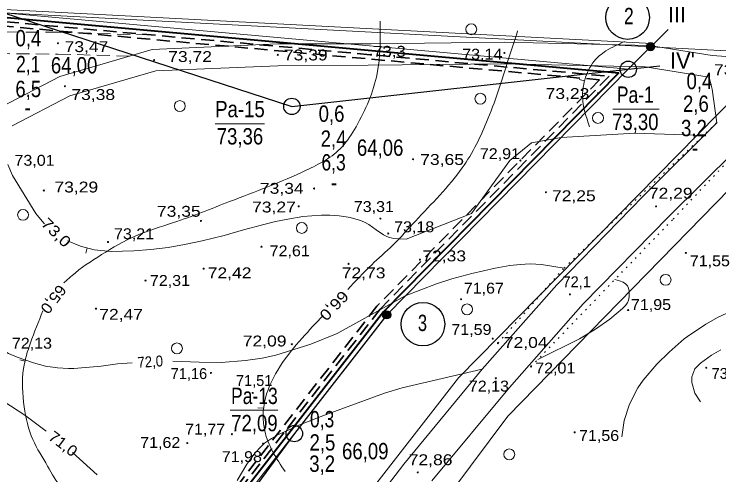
# Model space of a CAD drawing. Extents: x 628176 to 629009, y 6439913 to 6440496.
# Drawn here: x 628597 to 628726.4, y 6440342 to 6440426.6 of the extents above; entities that cross this region are included whole.
import ezdxf
from ezdxf.enums import TextEntityAlignment as Align

# ---------------------------------------------------------------- set-up
doc = ezdxf.new("R2010")
doc.units = 0
doc.header["$LTSCALE"] = 0.8
doc.linetypes.add('DOTTED', pattern=[1.5, 0.3, -1.2])
doc.linetypes.add('MEDIUM_DASHED', pattern=[4.5, 3, -1.5])
for name, color, linetype, lineweight in [('1', 7, 'Continuous', 13), ('10', 7, 'Continuous', 25), ('11', 7, 'Continuous', 13), ('12', 7, 'Continuous', 13), ('14', 7, 'Continuous', 25), ('16', 7, 'Continuous', 13), ('21', 7, 'MEDIUM_DASHED', 35), ('3', 7, 'Continuous', 13), ('6', 7, 'Continuous', 13)]:
    doc.layers.add(name, color=color, linetype=linetype, lineweight=lineweight)

msp = doc.modelspace()

# ---------------------------------------------------------------- hatches: boundary and pattern name
at = {"layer": '1'}
for points in [[(628605.1533, 6440421.2963, 1), (628604.9533, 6440421.2963, 1)], [(628687.1286, 6440419.5224, 1), (628686.9286, 6440419.5224, 1)], [(628622.7972, 6440418.1965, 1), (628622.5972, 6440418.1965, 1)], [(628645.5127, 6440419.1617, 1), (628645.3127, 6440419.1617, 1)], [(628662.6431, 6440419.1946, 1), (628662.4431, 6440419.1946, 1)], [(628606.4316, 6440413.4012, 1), (628606.2316, 6440413.4012, 1)], [(628704.3235, 6440412.1118, 1), (628704.1235, 6440412.1118, 1)], [(628670.3441, 6440399.9828, 1), (628670.1441, 6440399.9828, 1)], [(628690.0527, 6440399.7621, 1), (628689.8527, 6440399.7621, 1)], [(628602.5603, 6440394.2498, 1), (628602.3603, 6440394.2498, 1)], [(628652.1703, 6440394.6068, 1), (628651.9703, 6440394.6068, 1)], [(628694.7513, 6440393.9231, 1), (628694.5513, 6440393.9231, 1)], [(628649.3441, 6440391.3336, 1), (628649.1441, 6440391.3336, 1)], [(628714.9724, 6440391.3156, 1), (628714.7724, 6440391.3156, 1)], [(628631.4097, 6440388.6483, 1), (628631.2097, 6440388.6483, 1)], [(628664.365, 6440389.093, 1), (628664.165, 6440389.093, 1)], [(628665.8023, 6440386.3436, 1), (628665.6023, 6440386.3436, 1)], [(628614.341, 6440384.7869, 1), (628614.141, 6440384.7869, 1)], [(628642.5216, 6440383.9258, 1), (628642.3216, 6440383.9258, 1)], [(628720.4395, 6440382.7761, 1), (628720.2395, 6440382.7761, 1)], [(628658.5177, 6440380.7809, 1), (628658.3177, 6440380.7809, 1)], [(628671.6151, 6440381.5439, 1), (628671.4151, 6440381.5439, 1)], [(628631.9196, 6440379.8836, 1), (628631.7196, 6440379.8836, 1)], [(628621.2287, 6440377.6988, 1), (628621.0287, 6440377.6988, 1)], [(628679.1774, 6440374.2655, 1), (628678.9774, 6440374.2655, 1)], [(628699.1563, 6440375.1665, 1), (628698.9563, 6440375.1665, 1)], [(628612.1476, 6440372.5403, 1), (628611.9476, 6440372.5403, 1)], [(628709.8488, 6440372.2932, 1), (628709.6488, 6440372.2932, 1)], [(628684.9805, 6440367.0306, 1), (628684.7805, 6440367.0306, 1)], [(628685.9305, 6440366.2029, 1), (628685.7305, 6440366.2029, 1)], [(628648.0999, 6440365.9999, 1), (628647.8999, 6440365.9999, 1)], [(628692.0232, 6440361.8986, 1), (628691.8232, 6440361.8986, 1)], [(628724.1856, 6440361.6868, 1), (628723.9856, 6440361.6868, 1)], [(628633.2561, 6440360.7317, 1), (628633.0561, 6440360.7317, 1)], [(628685.5521, 6440359.7429, 1), (628685.3521, 6440359.7429, 1)], [(628640.9094, 6440357.0609, 1), (628640.7094, 6440357.0609, 1)], [(628637.0978, 6440349.4856, 1), (628636.8978, 6440349.4856, 1)], [(628700.0247, 6440349.8142, 1), (628699.8247, 6440349.8142, 1)], [(628628.9037, 6440347.8529, 1), (628628.7037, 6440347.8529, 1)], [(628642.8255, 6440347.757, 1), (628642.6255, 6440347.757, 1)], [(628671.218, 6440342.4629, 1), (628671.018, 6440342.4629, 1)]]:
    msp.add_hatch(color=256, dxfattribs=at).paths.add_polyline_path(points)
at = {"layer": '10'}
for points in [[(628714.5881, 6440420.6605, 1), (628713.0881, 6440420.6605, 1)], [(628666.1574, 6440371.4031, 1), (628664.6574, 6440371.4031, 1)]]:
    msp.add_hatch(color=256, dxfattribs=at).paths.add_polyline_path(points)

# ---------------------------------------------------------------- linework, layer by layer
at = {"layer": '1', "linetype": 'MEDIUM_DASHED'}
for p, q in [((628577.55, 6440423.51), (628605.07, 6440423.3)), ((628605.11, 6440423.3), (628621.66, 6440422.82)), ((628579.42, 6440419.49), (628605.04, 6440419.3)), ((628605, 6440419.3), (628618.11, 6440418.92))]:
    msp.add_line(p, q, dxfattribs=at)
at = {"layer": '1'}
for p, q in [((628645.41, 6440421.16), (628622.34, 6440420.16)), ((628662.54, 6440421.19), (628645.41, 6440421.16)), ((628687.03, 6440421.52), (628662.54, 6440421.19)), ((628713.68, 6440420.86), (628687.03, 6440421.52)), ((628725.2, 6440419.05), (628713.68, 6440420.86)), ((628622.34, 6440420.16), (628605.41, 6440415.18)), ((628737.64, 6440418.15), (628725.2, 6440419.05)), ((628645.41, 6440417.16), (628623.05, 6440416.23)), ((628662, 6440417.27), (628645.41, 6440417.16)), ((628687.03, 6440417.52), (628662, 6440417.27)), ((628712.88, 6440416.94), (628687.03, 6440417.52)), ((628724.62, 6440415.09), (628712.88, 6440416.94)), ((628623.05, 6440416.23), (628607.25, 6440411.62)), ((628605.41, 6440415.18), (628594.58, 6440409.55)), ((628725.14, 6440412.88), (628724.62, 6440415.09)), ((628726.04, 6440406.7), (628725.14, 6440412.88)), ((628607.25, 6440411.62), (628596.67, 6440406.14)), ((628712.53, 6440393.19), (628726.08, 6440406.74)), ((628717.21, 6440389.44), (628730.57, 6440402.75)), ((628696.63, 6440376.93), (628712.53, 6440393.19)), ((628701.48, 6440373.4), (628717.21, 6440389.44)), ((628682.96, 6440361.42), (628696.63, 6440376.93)), ((628687.94, 6440358.07), (628701.48, 6440373.4)), ((628668.54, 6440344), (628682.96, 6440361.42)), ((628673.69, 6440340.93), (628687.94, 6440358.07)), ((628658.58, 6440330.86), (628668.54, 6440344))]:
    msp.add_line(p, q, dxfattribs=at)
at = {"layer": '1', "linetype": 'DOTTED', "lineweight": 25}
for points in [[(628691.92, 6440361.9), (628718, 6440389), (628737.89, 6440410)], [(628685.83, 6440366.2), (628698, 6440380), (628726.08, 6440406.74)]]:
    msp.add_lwpolyline(points, dxfattribs=at)
at = {"layer": '1'}
for centre, radius in [((628680.9407, 6440423.8523), 1), ((628605.0533, 6440421.2963), 0.1), ((628687.0286, 6440419.5224), 0.1), ((628622.6972, 6440418.1965), 0.1), ((628645.4127, 6440419.1617), 0.1), ((628662.5431, 6440419.1946), 0.1), ((628606.3316, 6440413.4012), 0.1), ((628682.6148, 6440411.0956), 1), ((628704.2235, 6440412.1118), 0.1), ((628627.4365, 6440409.7628), 1), ((628704.208, 6440407.5652), 1), ((628670.2441, 6440399.9828), 0.1), ((628689.9527, 6440399.7621), 0.1), ((628602.4603, 6440394.2498), 0.1), ((628652.0703, 6440394.6068), 0.1), ((628694.6513, 6440393.9231), 0.1), ((628649.2441, 6440391.3336), 0.1), ((628714.8724, 6440391.3156), 0.1), ((628598.6478, 6440389.7706), 1), ((628631.3097, 6440388.6483), 0.1), ((628649.8277, 6440387.3716), 1), ((628664.265, 6440389.093), 0.1), ((628665.7023, 6440386.3436), 0.1), ((628614.241, 6440384.7869), 0.1), ((628642.4216, 6440383.9258), 0.1), ((628720.3395, 6440382.7761), 0.1), ((628658.4177, 6440380.7809), 0.1), ((628671.5151, 6440381.5439), 0.1), ((628631.8196, 6440379.8836), 0.1), ((628716.6172, 6440377.8348), 1), ((628621.1287, 6440377.6988), 0.1), ((628679.0774, 6440374.2655), 0.1), ((628699.0563, 6440375.1665), 0.1), ((628680.1651, 6440372.4058), 1), ((628612.0476, 6440372.5403), 0.1), ((628709.7488, 6440372.2932), 0.1), ((628626.9034, 6440365.2469), 1), ((628684.8805, 6440367.0306), 0.1), ((628685.8305, 6440366.2029), 0.1), ((628647.9999, 6440365.9999), 0.1), ((628691.9232, 6440361.8986), 0.1), ((628724.0856, 6440361.6868), 0.1), ((628633.1561, 6440360.7317), 0.1), ((628685.4521, 6440359.7429), 0.1), ((628640.8094, 6440357.0609), 0.1), ((628636.9978, 6440349.4856), 0.1), ((628699.9247, 6440349.8142), 0.1), ((628628.8037, 6440347.8529), 0.1), ((628642.7255, 6440347.757), 0.1), ((628687.9209, 6440345.7776), 1), ((628671.118, 6440342.4629), 0.1)]:
    msp.add_circle(centre, radius, dxfattribs=at)
at = {"layer": '10'}
for centre, radius in [((628709.6526, 6440426.0059), 4), ((628713.8381, 6440420.6605), 0.75), ((628672.0763, 6440369.6895), 4), ((628665.4074, 6440371.4031), 0.75)]:
    msp.add_circle(centre, radius, dxfattribs=at)
at = {"layer": '11'}
msp.add_line((628595.11, 6440426.87), (628709.76, 6440416.52), dxfattribs=at)
for points in [[(628595.11, 6440426.87), (628713.84, 6440420.66), (628709.76, 6440416.52)], [(628709.76, 6440416.52), (628665.41, 6440371.4), (628640.59, 6440339.47), (628612.95, 6440301.12), (628547.63, 6440210.77)]]:
    msp.add_lwpolyline(points, dxfattribs=at)
at = {"layer": '12'}
for p, q in [((628706.94, 6440409.2), (628715.43, 6440409.2)), ((628633.92, 6440406.47), (628643, 6440406.47)), ((628636.7, 6440353.92), (628645.42, 6440353.92))]:
    msp.add_line(p, q, dxfattribs=at)
at = {"layer": '12', "lineweight": 25}
for centre in [(628709.7629, 6440416.5158), (628647.9999, 6440409.6877), (628648.457, 6440349.5935)]:
    msp.add_circle(centre, 1.5, dxfattribs=at)
at = {"layer": '14'}
for q in [(628717.1, 6440423.79), (628715.56, 6440417.12)]:
    msp.add_line((628709.76, 6440416.52), q, dxfattribs=at)
for points in [[(628544.36, 6440425.1), (628595.11, 6440426.87), (628648, 6440409.69), (628709.76, 6440416.52)], [(628709.76, 6440416.52), (628665.41, 6440371.4), (628648.46, 6440349.59)], [(628648.46, 6440349.59), (628617.39, 6440307.28), (628547.63, 6440210.77), (628497.5, 6440118.54), (628474.19, 6440080.39)]]:
    msp.add_lwpolyline(points, dxfattribs=at)
at = {"layer": '16'}
for p, q in [((628700.77, 6440414.65), (628701.72, 6440414.36)), ((628598.03, 6440363.13), (628599.01, 6440362.9)), ((628641.78, 6440354.35), (628642.78, 6440354.27))]:
    msp.add_line(p, q, dxfattribs=at)
for points in [[(628664.23, 6440425.32), (628663.66, 6440415.72), (628659.79, 6440405.97), (628657.21, 6440402.25), (628650.62, 6440397.95), (628636.57, 6440392.21), (628626.25, 6440388.34), (628619.37, 6440385.91), (628613.06, 6440382.47), (628607.61, 6440378.6), (628606.11, 6440377.27)], [(628689.46, 6440423.6), (628688.03, 6440419.16), (628684.01, 6440407.41), (628679.28, 6440398.38), (628670.68, 6440388.63), (628666.53, 6440384.19), (628662.66, 6440380.6), (628658.25, 6440376.03)], [(628709.1, 6440421.6), (628705.66, 6440419.88), (628703.51, 6440418.01), (628701.79, 6440414.57), (628701.36, 6440411.42), (628702.65, 6440405.97)], [(628602.3, 6440372.11), (628600.02, 6440366.27), (628598.73, 6440361.54), (628598.87, 6440354.51), (628600.45, 6440348.49), (628603.17, 6440343.62), (628605.75, 6440339.61), (628610.62, 6440336.31), (628614.49, 6440334.3), (628621.23, 6440330.15), (628624.24, 6440328.14), (628629.83, 6440322.98)], [(628653.74, 6440371.29), (628649.9, 6440367.13), (628643.16, 6440356.09), (628642.73, 6440352.79), (628643.02, 6440350.07), (628646.75, 6440342.62)]]:
    msp.add_spline(points, degree=3, dxfattribs=at)
at = {"layer": '21'}
for p, q in [((628594.53, 6440424.51), (628704.5, 6440414.58)), ((628595.48, 6440425.23), (628706.25, 6440415.23))]:
    msp.add_line(p, q, dxfattribs=at)
at = {"layer": '21', "linetype": 'Continuous', "lineweight": 40}
for points in [[(628544.47, 6440424.31), (628575.21, 6440427.11), (628595.05, 6440426.07), (628708.01, 6440415.87)], [(628708.01, 6440415.87), (628664.8, 6440371.93), (628639.95, 6440339.95), (628612.3, 6440301.59), (628546.94, 6440211.19)]]:
    msp.add_lwpolyline(points, dxfattribs=at)
at = {"layer": '21'}
for points in [[(628704.5, 6440414.58), (628663.6, 6440372.99), (628638.67, 6440340.91), (628611, 6440302.53), (628546.02, 6440212.64)], [(628706.25, 6440415.23), (628664.2, 6440372.46), (628639.31, 6440340.43), (628611.65, 6440302.06), (628547.03, 6440212.69)]]:
    msp.add_lwpolyline(points, dxfattribs=at)
at = {"layer": '3'}
for p, q in [((628711, 6440404.75), (628723.71, 6440404.37)), ((628681, 6440390), (628688, 6440399.78)), ((628656.66, 6440389.59), (628654.97, 6440389.71)), ((628669, 6440385.32), (628681, 6440390)), ((628602.46, 6440388.25), (628602.6, 6440388.12)), ((628642.87, 6440388), (628645, 6440388.52)), ((628647.29, 6440389), (628645, 6440388.52)), ((628635.58, 6440386), (628639.14, 6440387)), ((628639.14, 6440387), (628642.87, 6440388)), ((628631.56, 6440385), (628635.58, 6440386)), ((628610.16, 6440382.72), (628610.41, 6440383.69)), ((628622.1, 6440383.39), (628619, 6440383.18)), ((628625.32, 6440383.79), (628622.1, 6440383.39)), ((628674.58, 6440377.11), (628677.36, 6440378)), ((628677.36, 6440378), (628681.02, 6440379)), ((628668.82, 6440374.87), (628674.58, 6440377.11)), ((628708.72, 6440372.55), (628706.39, 6440370.64)), ((628703.75, 6440368.8), (628706.39, 6440370.64)), ((628720.05, 6440367), (628717.25, 6440364.52)), ((628720.05, 6440367), (628720.63, 6440367.44)), ((628645.06, 6440364), (628651.48, 6440366)), ((628642.56, 6440363.44), (628645.06, 6440364)), ((628715, 6440362.35), (628717.25, 6440364.52)), ((628612.98, 6440362), (628616, 6440362.38)), ((628616, 6440362.38), (628618.67, 6440362.57)), ((628631, 6440362.72), (628626.15, 6440362.88)), ((628631, 6440362.72), (628635, 6440362.65)), ((628635, 6440362.65), (628639.52, 6440362.99)), ((628642.56, 6440363.44), (628639.52, 6440362.99)), ((628715, 6440362.35), (628712.48, 6440359.4)), ((628602.92, 6440350.04), (628599, 6440352.99)), ((628612.27, 6440342), (628607.74, 6440346.1))]:
    msp.add_line(p, q, dxfattribs=at)
for points in [[(628711, 6440404.75), (628697.46, 6440404), (628692, 6440403), (628688, 6440399.78)], [(628595.86, 6440399), (628596.71, 6440397), (628601, 6440390), (628602.46, 6440388.25)], [(628647.29, 6440389), (628650, 6440389.44), (628651.67, 6440389.61)], [(628654.97, 6440389.71), (628653.42, 6440389.73), (628651.67, 6440389.61)], [(628656.66, 6440389.59), (628658, 6440389.41), (628658.71, 6440389.26), (628660.61, 6440388.75), (628661.34, 6440388.45), (628662.11, 6440388), (628663.49, 6440387), (628664.84, 6440386.12), (628665.31, 6440385.86), (628665.75, 6440385.67), (628666.21, 6440385.52), (628666.68, 6440385.44), (628669, 6440385.32)], [(628606.84, 6440385), (628609.22, 6440384), (628611.73, 6440383.34)], [(628631.56, 6440385), (628628.27, 6440384.3), (628625.32, 6440383.79)], [(628619, 6440383.18), (628614.82, 6440383.07), (628611.73, 6440383.34)], [(628681.02, 6440379), (628685.35, 6440380), (628688, 6440380.46), (628689.94, 6440380.68), (628691.74, 6440380.75), (628693.84, 6440380.65), (628698, 6440380)], [(628707.31, 6440377.88), (628707.73, 6440377.79), (628708.18, 6440377.66), (628708.8, 6440377.41), (628709.24, 6440377.13), (628709.62, 6440376.74), (628709.83, 6440376.31), (628709.95, 6440375.76), (628709.95, 6440374.73), (628709.83, 6440374.13), (628709.62, 6440373.63)], [(628651.48, 6440366), (628656.32, 6440368), (628668.82, 6440374.87)], [(628709.62, 6440373.63), (628709.18, 6440373.03), (628708.72, 6440372.55)], [(628728.54, 6440372), (628726.27, 6440371), (628724, 6440369.68), (628720.63, 6440367.44)], [(628599, 6440352.99), (628591.21, 6440358), (628589.84, 6440359), (628588.72, 6440360), (628587.91, 6440361), (628587.28, 6440362), (628586.81, 6440363), (628585.8, 6440365), (628585.15, 6440366), (628584.23, 6440367), (628583.37, 6440367.52), (628582.13, 6440368), (628581.43, 6440368.16)], [(628693.16, 6440363.19), (628700.83, 6440367), (628703.75, 6440368.8)], [(628593.52, 6440366), (628594.87, 6440365), (628596, 6440364.31), (628597.58, 6440363.65), (628600.58, 6440362.58), (628602.79, 6440362), (628605, 6440361.65), (628607, 6440361.52), (628608, 6440361.54), (628612.98, 6440362)], [(628726.77, 6440365), (628725.03, 6440364), (628723, 6440362.54), (628722, 6440361.47), (628721.43, 6440360), (628721.43, 6440359), (628722, 6440357), (628723, 6440355.42)], [(628682.96, 6440361.42), (628668.28, 6440358), (628665, 6440357), (628654, 6440353), (628649, 6440351), (628648, 6440350.55), (628645.58, 6440349.4), (628644.26, 6440348.69), (628643.52, 6440348.23), (628643, 6440347.81), (628642.36, 6440347.21), (628641.22, 6440346), (628639.74, 6440344), (628637.99, 6440341)], [(628708.56, 6440349), (628709, 6440352), (628710, 6440355), (628711.51, 6440358), (628712.48, 6440359.4)]]:
    msp.add_lwpolyline(points, dxfattribs=at)
at = {"layer": '6'}
msp.add_line((628584.56, 6440428.02), (628714.07, 6440421.25), dxfattribs=at)
for points in [[(628713.84, 6440420.66), (628737.18, 6440419.44), (628678.6, 6440359.86), (628654.6, 6440328.98), (628627.14, 6440290.88), (628627.14, 6440290.88), (628627.14, 6440290.88), (628562.66, 6440201.7), (628536.24, 6440148.38), (628489.22, 6440071.42), (628480.02, 6440052.78), (628457.03, 6440037.16), (628421.17, 6440028.67)], [(628753.89, 6440420.62), (628687.68, 6440352.8), (628636.46, 6440284.16), (628572.54, 6440195.74), (628546.32, 6440142.82), (628546.32, 6440142.82), (628546.32, 6440142.82), (628498.7, 6440064.9), (628484.24, 6440046.28), (628473.72, 6440036.18), (628464.05, 6440028.67)]]:
    msp.add_lwpolyline(points, dxfattribs=at)

# ---------------------------------------------------------------- texts
at = {"layer": '1'}
for s, width, p in [('73,47', 1.2, (628606.28, 6440419.67)), ('73,3', 1.15, (628662.93, 6440418.81)), ('73,72', 1.2, (628625.3, 6440417.85)), ('73,39', 1.2, (628646.54, 6440418.14)), ('73,14', 1.1, (628679.28, 6440418.28)), ('73,39', 1.2, (628725.5, 6440415.43)), ('73,38', 1.2, (628607.52, 6440410.87)), ('73,23', 1.2, (628694.59, 6440411.05)), ('72,91', 1.1, (628682.52, 6440400.01)), ('73,01', 1.1, (628597.08, 6440398.79)), ('73,65', 1.2, (628671.57, 6440398.94)), ('73,29', 1.2, (628604.41, 6440393.88)), ('73,34', 1.2, (628642.14, 6440393.64)), ('72,29', 1.2, (628713.55, 6440392.74)), ('72,25', 1.2, (628695.76, 6440392.28)), ('73,27', 1.2, (628640.7, 6440390.21)), ('73,31', 1.1, (628659.38, 6440390.29)), ('73,35', 1.2, (628623.23, 6440389.42)), ('73,18', 1.1, (628666.78, 6440386.58)), ('73,21', 1.1, (628615.35, 6440385.3)), ('72,61', 1.1, (628643.93, 6440382.16)), ('72,33', 1.2, (628671.95, 6440381.23)), ('71,55', 1.1, (628721.07, 6440380.33)), ('72,42', 1.2, (628632.56, 6440378.11)), ('72,73', 1.2, (628657.16, 6440378.11)), ('72,31', 1.1, (628621.94, 6440376.71)), ('71,67', 1.1, (628679.57, 6440375.31)), ('71,95', 1.1, (628710.26, 6440372.29)), ('72,47', 1.2, (628612.64, 6440370.49)), ('71,59', 1.1, (628677.29, 6440367.71)), ('72,09', 1.2, (628638.99, 6440365.6)), ('72,13', 1.1, (628596.6, 6440365.19)), ('72,04', 1.2, (628686.92, 6440365.33)), ('72,01', 1.1, (628692.68, 6440360.63)), ('72,13', 1.1, (628680.5, 6440357.32)), ('71,77', 1.1, (628628.4, 6440349.4)), ('71,56', 1.1, (628700.73, 6440348.24)), ('71,62', 1.1, (628620.16, 6440346.96)), ('71,98', 1.1, (628635.14, 6440344.36)), ('72,86', 1.2, (628669.46, 6440343.79))]:
    msp.add_text(s, height=2, dxfattribs=dict(at, width=width)).set_placement(p)
for s, p in [('72,1', (628697.7, 6440376.48)), ('71,16', (628625.76, 6440359.61)), ('73,11', (628725.07, 6440359.64)), ('71,51', (628637.74, 6440358.34))]:
    msp.add_text(s, height=2, dxfattribs=at).set_placement(p)
at = {"layer": '10'}
for s, width, p in [('2', 0.8, (628709.87, 6440424.79)), ('3', 0.75, (628671.985, 6440368.43))]:
    msp.add_text(s, height=3, dxfattribs=dict(at, width=width)).set_placement(p, align=Align.CENTER)
at = {"layer": '12'}
for s, width, p in [('0,4', 0.85, (628599.63, 6440420.73)), ('2,1', 0.8, (628599.595, 6440415.96)), ('64,00', 0.85, (628608.025, 6440415.75)), ('0,4', 0.85, (628722.83, 6440412.86)), ('6,5', 0.85, (628599.605, 6440411.4)), ('Pa-1', 0.8, (628711.055, 6440410.35)), ('2,6', 0.85, (628722.185, 6440408.69)), ('Pa-15', 0.85, (628638.475, 6440407.7)), ('-', 0.85, (628599.515, 6440408)), ('0,6', 0.85, (628655.29, 6440406.86)), ('73,30', 0.85, (628711.055, 6440405.35)), ('3,2', 0.85, (628721.825, 6440404.22)), ('73,36', 0.85, (628638.475, 6440402.7)), ('2,4', 0.85, (628655.66, 6440402.28)), ('64,06', 0.85, (628664.215, 6440400.62)), ('-', 0.85, (628722.025, 6440400.6)), ('6,3', 0.8, (628655.66, 6440397.92)), ('-', 0.85, (628655.745, 6440394.22)), ('Pa-13', 0.8, (628641.125, 6440355.02)), ('0,3', 0.8, (628653.56, 6440350.74)), ('72,09', 0.85, (628641.125, 6440350.02)), ('2,5', 0.85, (628653.615, 6440346.47)), ('66,09', 0.85, (628661.48, 6440344.87)), ('3,2', 0.85, (628653.565, 6440342.56))]:
    msp.add_text(s, height=3, dxfattribs=dict(at, width=width)).set_placement(p, align=Align.CENTER)
at = {"layer": '14'}
for s, p in [('III', (628718.71, 6440425.13)), ("IV'", (628719.715, 6440416.65))]:
    msp.add_text(s, height=3, dxfattribs=at).set_placement(p, align=Align.CENTER)
at = {"layer": '16'}
for s, rotation, width, p in [('65,0', 232.588, 1.1, (628603.4409, 6440374.8625)), ('66,0', 226.373, 1.2, (628655.0395, 6440373.77))]:
    msp.add_text(s, height=2, rotation=rotation, dxfattribs=dict(at, width=width)).set_placement(p, align=Align.CENTER)
at = {"layer": '3'}
for s, rotation, width, p in [('73,0', 315.734, 1.2, (628601.8, 6440387.98)), ('72,0', 4.03, 0.9, (628619.74, 6440361.64)), ('71,0', 323.074, 1.1, (628603.12, 6440348.64))]:
    msp.add_text(s, height=2, rotation=rotation, dxfattribs=dict(at, width=width)).set_placement(p)

doc.saveas('drawing.dxf')
